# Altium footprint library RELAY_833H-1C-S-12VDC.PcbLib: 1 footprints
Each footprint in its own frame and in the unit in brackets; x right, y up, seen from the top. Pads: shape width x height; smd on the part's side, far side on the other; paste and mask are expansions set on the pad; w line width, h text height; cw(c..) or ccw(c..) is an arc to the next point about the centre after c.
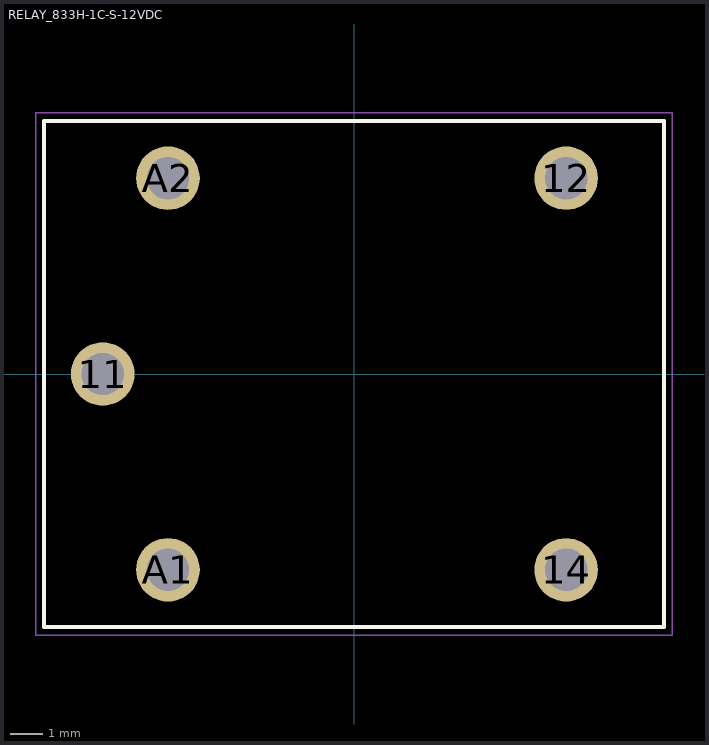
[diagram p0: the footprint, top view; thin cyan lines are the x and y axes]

## RELAY_833H-1C-S-12VDC [mm]
height 15.5
pads (5):
  round 1.95 hole 1.3: 11(-7.7,0) 12(6.5,6) 14(6.5,-6) A1(-5.7,-6) A2(-5.7,6)
Top Overlay:
  lines w0.127: -9.5,-7.75 -9.5,7.75 9.5,7.75 9.5,-7.75 -9.5,-7.75
Mechanical 13:
  lines w0.127: -9.5,-7.75 -9.5,7.75 9.5,7.75 9.5,-7.75 -9.5,-7.75
Mechanical 15:
  lines w0.05: -9.75,-8 -9.75,8 9.75,8 9.75,-8 -9.75,-8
